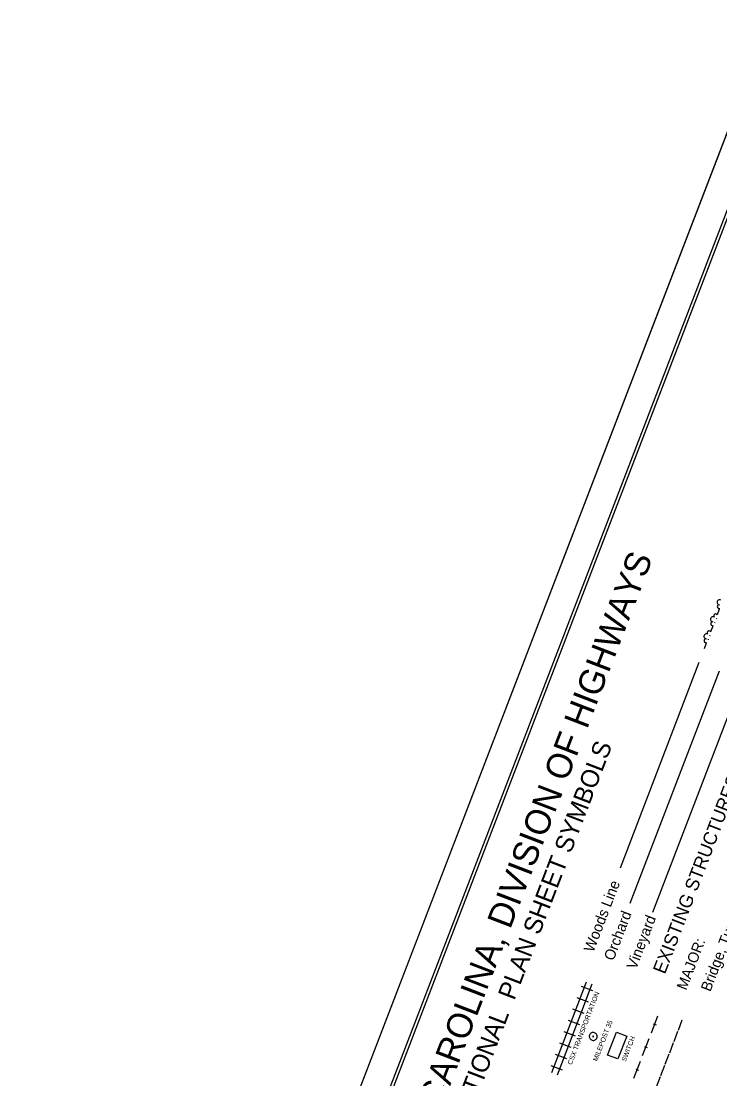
# Model space of a CAD drawing. Extents: x 1015221 to 1064345, y 619216 to 647967.
# Drawn here: x 1042814 to 1047324, y 630539 to 637366 of the extents above; entities that cross this region are included whole.
import ezdxf

# ---------------------------------------------------------------- set-up
doc = ezdxf.new("R2010")
doc.units = 0
for name, color, linetype in [('Default', 7, 'Continuous'), ('Sheet Cutting Line CELL', 7, 'Continuous'), ('Sheet Plot Border Inside CELL', 7, 'Continuous'), ('Sheet Plot Border Outside CELL', 7, 'Continuous'), ('Sheet Symbology CELL', 7, 'Continuous')]:
    doc.layers.add(name, color=color, linetype=linetype)

msp = doc.modelspace()

# ---------------------------------------------------------------- linework, layer by layer
at = {"layer": 'Default'}
for p, q in [((1047308.2, 633536.2), (1047322.3, 633572.8)), ((1047301.9, 633508.8), (1047303.3, 633512.4)), ((1047266, 633426.3), (1047280.1, 633462.9)), ((1047292.1, 633483.1), (1047293.5, 633486.8)), ((1047249.8, 633373.3), (1047251.2, 633376.9)), ((1047259.7, 633398.9), (1047261.1, 633402.6)), ((1047223.8, 633316.4), (1047237.9, 633353.1)), ((1047188.9, 633225.7), (1046679.3, 631899.1)), ((1047318.6, 633171.1), (1046742, 631670.1)), ((1047465.1, 633114.8), (1046888.4, 631613.8)), ((1046504.2, 631107.8), (1046431, 631136)), ((1046435.2, 631092.3), (1046463.3, 631165.5)), ((1046471.8, 631078.2), (1046500, 631151.5)), ((1046476.1, 631034.6), (1046402.8, 631062.7)), ((1046407.1, 631019.1), (1046435.2, 631092.3)), ((1046443.7, 631005), (1046471.8, 631078.2)), ((1046447.9, 630961.3), (1046374.7, 630989.5)), ((1046378.9, 630945.8), (1046407.1, 631019.1)), ((1046415.5, 630931.7), (1046443.7, 631005)), ((1046419.8, 630888.1), (1046346.5, 630916.2)), ((1046350.8, 630872.6), (1046378.9, 630945.8)), ((1046387.4, 630858.5), (1046415.5, 630931.7)), ((1046881.4, 630836.8), (1046923.6, 630946.7)), ((1047056, 630853.8), (1047081.3, 630919.7)), ((1046391.6, 630814.8), (1046318.4, 630843)), ((1046322.6, 630799.3), (1046350.8, 630872.6)), ((1046359.3, 630785.3), (1046387.4, 630858.5)), ((1046893.3, 630895.3), (1046911.7, 630888.2)), ((1047027.9, 630780.5), (1047053.2, 630846.5)), ((1046363.5, 630741.6), (1046290.3, 630769.7)), ((1046294.5, 630726.1), (1046322.6, 630799.3)), ((1046331.1, 630712), (1046359.3, 630785.3)), ((1046825.1, 630690.3), (1046867.3, 630800.2)), ((1046999.7, 630707.3), (1047025.1, 630773.2)), ((1046335.4, 630668.4), (1046262.1, 630696.5)), ((1046266.4, 630652.8), (1046294.5, 630726.1)), ((1046303, 630638.8), (1046331.1, 630712)), ((1046837.1, 630748.8), (1046855.4, 630741.7)), ((1046971.6, 630634.1), (1046996.9, 630700)), ((1046238.2, 630579.6), (1046266.4, 630652.8)), ((1046274.8, 630565.5), (1046303, 630638.8)), ((1046768.8, 630543.8), (1046811, 630653.7)), ((1046943.5, 630560.8), (1046968.8, 630626.7)), ((1046307.2, 630595.1), (1046234, 630623.3)), ((1046780.8, 630602.3), (1046799.1, 630595.3)), ((1046915.3, 630487.6), (1046940.6, 630553.5))]:
    msp.add_line(p, q, dxfattribs=at)
for points in [[(1046515.2, 630836.8), (1046510.3, 630838.1), (1046505, 630838.5), (1046499.8, 630837.8), (1046495.2, 630835.8), (1046490.9, 630833.1), (1046486.8, 630829.7), (1046484.3, 630825.8), (1046481.8, 630820.7), (1046480.9, 630815.6), (1046480.7, 630810.8), (1046481.4, 630805.6), (1046483.5, 630800.9), (1046486.6, 630796.5), (1046490.2, 630792.9), (1046494.6, 630790.1), (1046499.3, 630788.3), (1046504.5, 630787.4), (1046509.5, 630787.7), (1046514.9, 630788.9), (1046519.5, 630791), (1046523.5, 630794.3), (1046526.6, 630798), (1046529.3, 630802.4), (1046530.9, 630807.8), (1046531.6, 630812.5), (1046530.8, 630817.7), (1046529.5, 630822.6), (1046527.4, 630827.2), (1046524, 630831.2), (1046519.8, 630834.5), (1046515.2, 630836.8)], [(1046503.6, 630815.1), (1046503.1, 630813.6), (1046503.5, 630811.8), (1046504.5, 630810.3), (1046506.2, 630810.3), (1046507.9, 630810.7), (1046509, 630811.9), (1046509, 630813.5), (1046508.4, 630814.8), (1046506.7, 630816), (1046505.1, 630816.1), (1046503.6, 630815.1)]]:
    msp.add_lwpolyline(points, dxfattribs=at)
msp.add_lwpolyline([(1046599.5, 630693), (1046655.8, 630839.4), (1046722.4, 630813.8), (1046666.1, 630667.4)], close=True, dxfattribs=at)
for centre, radius, start, end in [((1047321.5, 633614.7), 16.2, 54.94678, 263.01927), ((1047318.9, 633586.3), 12.4, 87.41797, 288.21454), ((1047279.3, 633504.8), 16.2, 54.94678, 263.01927), ((1047296.4, 633527.7), 12.4, 29.7515, 230.54807), ((1047254.2, 633417.8), 12.4, 29.7515, 230.54807), ((1047276.7, 633476.4), 12.4, 87.41797, 288.21454), ((1047237, 633395), 16.2, 54.94678, 263.01927), ((1047234.5, 633366.5), 12.4, 87.41797, 288.21454)]:
    msp.add_arc(centre, radius, start, end, dxfattribs=at)
at = {"layer": 'Sheet Cutting Line CELL'}
msp.add_line((1047645.6, 637365.6), (1042813.9, 624789.8), dxfattribs=at)
at = {"layer": 'Sheet Plot Border Inside CELL'}
msp.add_lwpolyline([(1050898.2, 621795.3), (1055679.6, 634240.3), (1047800.3, 637267.6), (1043018.9, 624822.5)], close=True, dxfattribs=at)
at = {"layer": 'Sheet Plot Border Outside CELL'}
msp.add_lwpolyline([(1051028.5, 621633.8), (1055860.2, 634209.5), (1047645.6, 637365.6), (1042813.9, 624789.8)], close=True, dxfattribs=at)
at = {"layer": 'Sheet Symbology CELL'}
msp.add_lwpolyline([(1047783.5, 637166.9), (1043479.8, 625965.2), (1051313.4, 622955.5), (1055617.1, 634157.2)], close=True, dxfattribs=at)

# ---------------------------------------------------------------- texts
at = {"layer": 'Default'}
for s, height, p in [('STATE OF NORTH CAROLINA, DIVISION OF HIGHWAYS', 163.31, (1044821.1, 628509.7)), ('CONVENTIONAL  PLAN SHEET SYMBOLS', 116.65, (1045524.1, 629811.2)), ('EXISTING STRUCTURES:', 86.308, (1046969.2, 631210.1)), ('Bridge, Tunnel or Box Culvert', 68.654, (1047262.1, 631097.5)), ('Woods Line', 68.65, (1046506.9, 631351.4)), ('Orchard', 68.65, (1046636.6, 631296.8)), ('Vineyard', 68.65, (1046783.1, 631240.5)), ('MAJOR:', 68.65, (1047106.8, 631106.6)), ('CSX TRANSPORTATION', 31.385, (1046367.7, 630627)), ('MILEPOST 35', 31.385, (1046532.4, 630649.4)), ('SWITCH', 31.38, (1046716.6, 630647.5))]:
    msp.add_text(s, height=height, rotation=68.98302, dxfattribs=at).set_placement(p)

doc.saveas('drawing.dxf')
